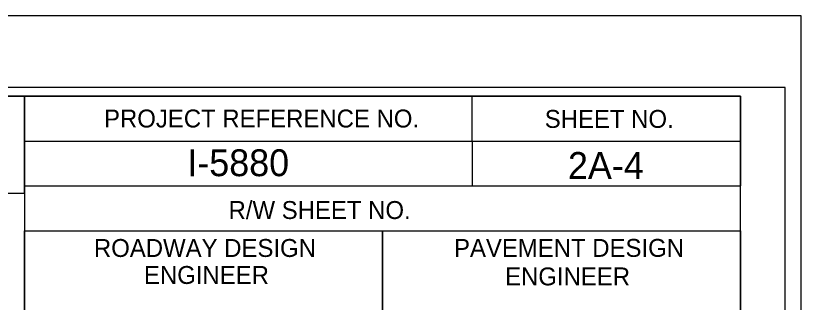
# Model space of a CAD drawing. Extents: x 1640342 to 1730599, y 538663 to 843747.
# Drawn here: x 1730133.49 to 1730177.39, y 539590.64 to 539606.64 of the extents above; entities that cross this region are included whole.
import ezdxf

# ---------------------------------------------------------------- set-up
doc = ezdxf.new("R2010")
doc.units = 0
for name, color, linetype in [('Prop Dimension Text', 7, 'Continuous'), ('Sheet Data Field CELL', 7, 'Continuous'), ('Sheet Plan CELL', 7, 'Continuous'), ('Sheet Plan Layout CELL', 7, 'Continuous'), ('Sheet Plot Border Inside CELL', 7, 'Continuous'), ('Sheet Plot Border Outside CELL', 7, 'Continuous')]:
    doc.layers.add(name, color=color, linetype=linetype)

msp = doc.modelspace()

# ---------------------------------------------------------------- linework, layer by layer
at = {"layer": 'Prop Dimension Text'}
msp.add_lwpolyline([(1730104.001, 539596.732), (1730133.983, 539596.732), (1730133.983, 539602.142), (1730104.001, 539602.142)], close=True, dxfattribs=at)
at = {"layer": 'Sheet Plan CELL'}
for p, q in [((1730158.985, 539602.127), (1730158.995, 539597.127)), ((1730133.98, 539599.632), (1730173.99, 539599.63)), ((1730133.983, 539597.125), (1730173.99, 539597.13)), ((1730133.983, 539597.125), (1730173.99, 539597.13)), ((1730133.983, 539597.125), (1730133.983, 539594.627)), ((1730153.993, 539594.627), (1730153.995, 539572.135))]:
    msp.add_line(p, q, dxfattribs=at)
for points in [[(1729873.99, 539392.14), (1729873.985, 539602.135), (1730133.983, 539602.142), (1730133.985, 539572.13), (1730173.993, 539572.127), (1730173.993, 539392.14)], [(1730173.998, 539602.14), (1729873.99, 539602.14), (1729873.99, 539392.14), (1730173.993, 539392.14)], [(1730133.983, 539602.142), (1730173.998, 539602.14), (1730173.99, 539597.13), (1730133.983, 539597.125)], [(1730133.983, 539594.627), (1730153.993, 539594.627), (1730153.993, 539572.125), (1730133.985, 539572.13)], [(1730153.993, 539594.627), (1730173.99, 539594.63), (1730173.993, 539572.127), (1730153.993, 539572.125)]]:
    msp.add_lwpolyline(points, close=True, dxfattribs=at)
at = {"layer": 'Sheet Plan Layout CELL'}
msp.add_lwpolyline([(1730126.14, 539559.842), (1730173.995, 539559.842), (1730174, 539602.14), (1730126.14, 539602.14)], close=True, dxfattribs=at)
at = {"layer": 'Sheet Plot Border Inside CELL'}
msp.add_lwpolyline([(1729843.293, 539391.637), (1730176.49, 539391.64), (1730176.493, 539602.637), (1729843.293, 539602.637)], close=True, dxfattribs=at)
at = {"layer": 'Sheet Plot Border Outside CELL'}
msp.add_lwpolyline([(1729840.693, 539387.637), (1730177.393, 539387.637), (1730177.393, 539606.637), (1729840.693, 539606.637)], close=True, dxfattribs=at)

# ---------------------------------------------------------------- texts
at = {"layer": 'Sheet Data Field CELL'}
for s, p in [('I-5880', (1730143.079, 539597.677)), ('2A-4', (1730164.353, 539597.525))]:
    msp.add_text(s, height=1.5, rotation=0, dxfattribs=at).set_placement(p)
at = {"layer": 'Sheet Plan CELL'}
for s, height, p in [('PROJECT REFERENCE NO.', 1.00002, (1730138.423, 539600.397)), ('SHEET NO.', 1, (1730163.055, 539600.375)), ('R/W SHEET NO.', 1.00002, (1730145.383, 539595.287)), ('ROADWAY DESIGN', 1.00002, (1730137.858, 539593.167)), ('PAVEMENT DESIGN', 1.00002, (1730157.984, 539593.172)), ('ENGINEER', 1, (1730140.655, 539591.66)), ('ENGINEER', 1, (1730160.838, 539591.58))]:
    msp.add_text(s, height=height, rotation=0, dxfattribs=at).set_placement(p)

doc.saveas('drawing.dxf')
